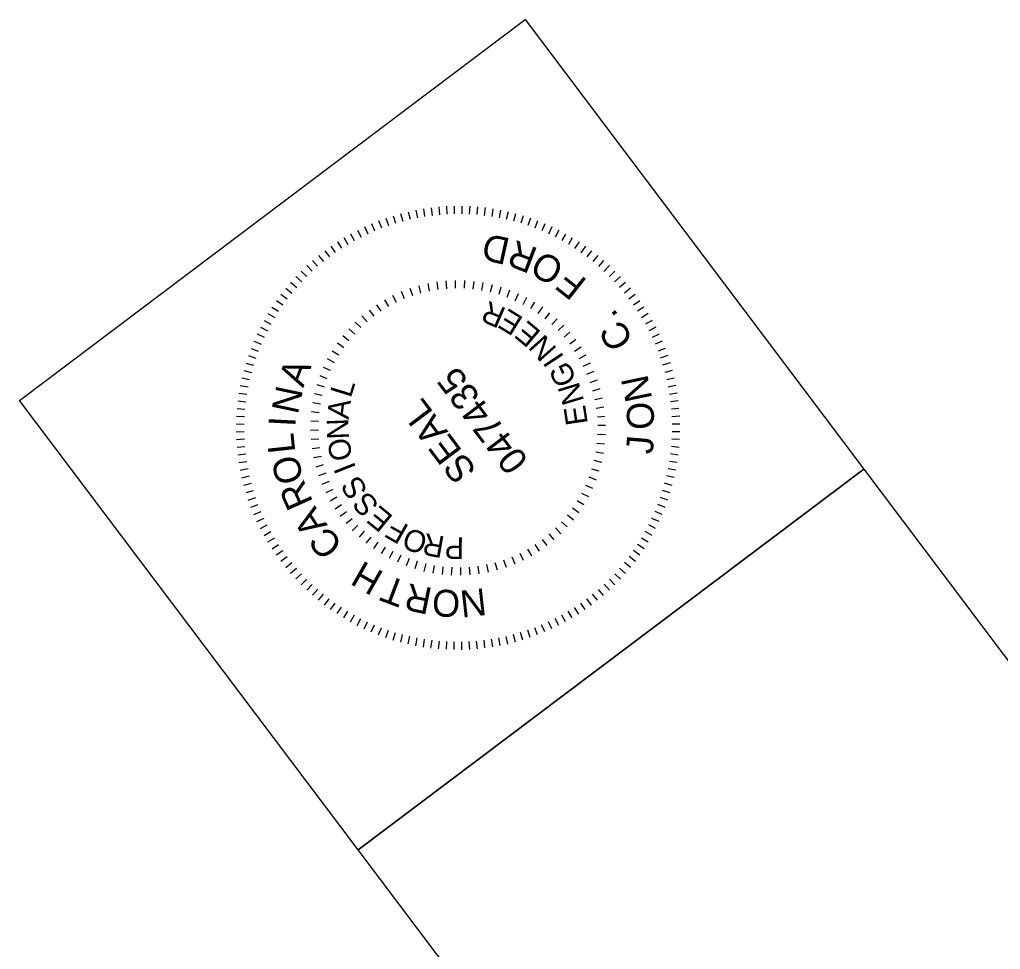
# Model space of a CAD drawing. Extents: x 1261689 to 1263694, y 776294 to 778298.
# Drawn here: x 1261689.1 to 1261863.3, y 777796.6 to 777961.8 of the extents above; entities that cross this region are included whole.
import ezdxf

# ---------------------------------------------------------------- set-up
doc = ezdxf.new("R2010")
doc.units = 0
doc.layers.add('Sheet Border Standard 30in CELL', color=7, linetype='Continuous')
doc.layers.add('Sheet PE Seal Cell', color=7, linetype='Continuous')

msp = doc.modelspace()

# ---------------------------------------------------------------- linework, layer by layer
at = {"layer": 'Sheet Border Standard 30in CELL'}
for points in [[(1261749.21, 777814.3), (1261689.06, 777894.15), (1261778.9, 777961.82), (1261839.04, 777881.96)], [(1261809.38, 777734.41), (1261749.21, 777814.3), (1261839.04, 777881.96), (1261899.22, 777802.07)]]:
    msp.add_lwpolyline(points, close=True, dxfattribs=at)
at = {"layer": 'Sheet PE Seal Cell'}
for p, q in [((1261760.81, 777928.21), (1261761, 777926.85)), ((1261762.17, 777928.39), (1261762.36, 777927.04)), ((1261763.56, 777928.54), (1261763.65, 777927.16)), ((1261764.91, 777928.66), (1261764.99, 777927.27)), ((1261766.28, 777928.67), (1261766.29, 777927.3)), ((1261767.65, 777928.67), (1261767.62, 777927.28)), ((1261769.05, 777928.65), (1261768.96, 777927.26)), ((1261770.4, 777928.53), (1261770.28, 777927.18)), ((1261771.75, 777928.41), (1261771.59, 777927.03)), ((1261773.12, 777928.18), (1261772.93, 777926.84)), ((1261754.15, 777926.55), (1261754.58, 777925.25)), ((1261755.44, 777926.97), (1261755.83, 777925.66)), ((1261756.76, 777927.37), (1261757.12, 777926.02)), ((1261758.11, 777927.66), (1261758.42, 777926.35)), ((1261759.44, 777927.95), (1261759.73, 777926.61)), ((1261774.49, 777927.95), (1261774.24, 777926.62)), ((1261775.83, 777927.69), (1261775.53, 777926.33)), ((1261777.18, 777927.33), (1261776.82, 777925.99)), ((1261778.5, 777926.95), (1261778.11, 777925.63)), ((1261779.81, 777926.56), (1261779.35, 777925.25)), ((1261750.31, 777925.03), (1261750.91, 777923.75)), ((1261751.58, 777925.57), (1261752.12, 777924.3)), ((1261752.85, 777926.11), (1261753.35, 777924.81)), ((1261781.07, 777926.07), (1261780.61, 777924.77)), ((1261782.36, 777925.54), (1261781.82, 777924.3)), ((1261783.63, 777924.99), (1261783.03, 777923.71)), ((1261746.68, 777923.08), (1261747.4, 777921.89)), ((1261747.86, 777923.73), (1261748.52, 777922.55)), ((1261749.09, 777924.42), (1261749.73, 777923.16)), ((1261784.84, 777924.41), (1261784.22, 777923.16)), ((1261786.07, 777923.72), (1261785.41, 777922.55)), ((1261787.25, 777923.05), (1261786.57, 777921.88)), ((1261744.35, 777921.56), (1261745.15, 777920.42)), ((1261745.51, 777922.32), (1261746.24, 777921.18)), ((1261788.45, 777922.32), (1261787.67, 777921.14)), ((1261789.57, 777921.56), (1261788.76, 777920.4)), ((1261742.16, 777919.91), (1261743.04, 777918.83)), ((1261743.27, 777920.75), (1261744.11, 777919.64)), ((1261790.66, 777920.76), (1261789.86, 777919.67)), ((1261791.77, 777919.91), (1261790.9, 777918.84)), ((1261740.1, 777918.12), (1261741.04, 777917.1)), ((1261741.11, 777919), (1261742, 777917.99)), ((1261792.8, 777919.02), (1261791.9, 777917.98)), ((1261793.85, 777918.12), (1261792.88, 777917.09)), ((1261738.14, 777916.18), (1261739.18, 777915.21)), ((1261739.11, 777917.13), (1261740.06, 777916.17)), ((1261794.83, 777917.11), (1261793.87, 777916.17)), ((1261795.79, 777916.17), (1261794.77, 777915.22)), ((1261737.21, 777915.17), (1261738.29, 777914.23)), ((1261760.37, 777913.19), (1261760.02, 777914.53)), ((1261761.89, 777913.54), (1261761.62, 777914.96)), ((1261763.41, 777913.85), (1261763.22, 777915.21)), ((1261764.97, 777914.01), (1261764.86, 777915.43)), ((1261766.52, 777914.1), (1261766.51, 777915.46)), ((1261768.09, 777914.08), (1261768.14, 777915.44)), ((1261769.65, 777913.93), (1261769.81, 777915.31)), ((1261771.19, 777913.71), (1261771.42, 777915.08)), ((1261772.73, 777913.43), (1261773.05, 777914.75)), ((1261774.24, 777913.01), (1261774.64, 777914.32)), ((1261796.7, 777915.11), (1261795.66, 777914.2)), ((1261735.48, 777913.03), (1261736.59, 777912.19)), ((1261736.35, 777914.1), (1261737.42, 777913.23)), ((1261756.03, 777911.53), (1261755.39, 777912.79)), ((1261757.46, 777912.19), (1261756.89, 777913.49)), ((1261758.91, 777912.73), (1261758.44, 777914.07)), ((1261775.7, 777912.5), (1261776.17, 777913.8)), ((1261777.12, 777911.88), (1261777.72, 777913.17)), ((1261778.53, 777911.2), (1261779.19, 777912.48)), ((1261797.58, 777914.1), (1261796.5, 777913.23)), ((1261798.42, 777912.99), (1261797.31, 777912.15)), ((1261733.9, 777910.75), (1261735.05, 777910.01)), ((1261734.7, 777911.9), (1261735.83, 777911.12)), ((1261753.28, 777910), (1261752.53, 777911.16)), ((1261754.64, 777910.84), (1261753.95, 777912)), ((1261779.87, 777910.48), (1261780.61, 777911.63)), ((1261781.18, 777909.6), (1261782, 777910.76)), ((1261799.26, 777911.88), (1261798.12, 777911.08)), ((1261799.99, 777910.75), (1261798.82, 777910)), ((1261733.19, 777909.62), (1261734.38, 777908.9)), ((1261750.8, 777908.13), (1261749.89, 777909.18)), ((1261752.03, 777909.12), (1261751.2, 777910.22)), ((1261782.42, 777908.68), (1261783.29, 777909.74)), ((1261800.75, 777909.58), (1261799.56, 777908.86)), ((1261732.5, 777908.37), (1261733.71, 777907.73)), ((1261749.66, 777907.09), (1261748.7, 777908.05)), ((1261783.61, 777907.65), (1261784.58, 777908.68)), ((1261784.72, 777906.57), (1261785.75, 777907.53)), ((1261801.43, 777908.36), (1261800.25, 777907.7)), ((1261731.27, 777905.96), (1261732.48, 777905.37)), ((1261731.85, 777907.17), (1261733.1, 777906.55)), ((1261747.58, 777904.75), (1261746.49, 777905.66)), ((1261748.62, 777905.94), (1261747.54, 777906.88)), ((1261785.79, 777905.39), (1261786.84, 777906.3)), ((1261802.09, 777907.17), (1261800.83, 777906.53)), ((1261802.67, 777905.92), (1261801.42, 777905.35)), ((1261730.68, 777904.66), (1261731.96, 777904.14)), ((1261746.66, 777903.51), (1261745.51, 777904.33)), ((1261786.79, 777904.23), (1261787.9, 777905.06)), ((1261803.24, 777904.68), (1261801.97, 777904.14)), ((1261729.7, 777902.13), (1261731.01, 777901.68)), ((1261730.19, 777903.4), (1261731.45, 777902.91)), ((1261745.79, 777902.2), (1261744.6, 777902.91)), ((1261787.66, 777902.91), (1261788.8, 777903.7)), ((1261788.47, 777901.59), (1261789.7, 777902.28)), ((1261803.75, 777903.38), (1261802.48, 777902.91)), ((1261804.22, 777902.11), (1261802.88, 777901.65)), ((1261729.28, 777900.8), (1261730.59, 777900.41)), ((1261745.02, 777900.83), (1261743.78, 777901.52)), ((1261789.2, 777900.23), (1261790.49, 777900.83)), ((1261804.64, 777900.82), (1261803.29, 777900.4)), ((1261728.89, 777899.48), (1261730.24, 777899.12)), ((1261743.73, 777898.01), (1261742.43, 777898.53)), ((1261744.31, 777899.46), (1261743.06, 777900.02)), ((1261789.86, 777898.8), (1261791.13, 777899.34)), ((1261805.01, 777899.47), (1261803.69, 777899.14)), ((1261728.27, 777896.79), (1261729.64, 777896.57)), ((1261728.57, 777898.16), (1261729.93, 777897.86)), ((1261743.22, 777896.54), (1261741.91, 777896.93)), ((1261790.4, 777897.36), (1261791.74, 777897.82)), ((1261805.36, 777898.12), (1261804.02, 777897.84)), ((1261805.65, 777896.79), (1261804.28, 777896.53)), ((1261728.02, 777895.46), (1261729.42, 777895.26)), ((1261742.83, 777895.06), (1261741.47, 777895.35)), ((1261790.89, 777895.85), (1261792.2, 777896.25)), ((1261805.88, 777895.45), (1261804.51, 777895.2)), ((1261727.86, 777894.08), (1261729.24, 777893.92)), ((1261742.51, 777893.49), (1261741.14, 777893.72)), ((1261791.24, 777894.33), (1261792.63, 777894.64)), ((1261806.06, 777894.09), (1261804.71, 777893.91)), ((1261727.7, 777892.7), (1261729.09, 777892.61)), ((1261742.29, 777891.95), (1261740.91, 777892.11)), ((1261791.51, 777892.78), (1261792.88, 777893.04)), ((1261806.21, 777892.7), (1261804.86, 777892.58)), ((1261727.59, 777889.98), (1261728.94, 777889.92)), ((1261727.61, 777891.38), (1261729, 777891.29)), ((1261742.18, 777890.42), (1261740.79, 777890.45)), ((1261791.71, 777891.25), (1261793.06, 777891.37)), ((1261806.33, 777891.35), (1261804.94, 777891.27)), ((1261806.37, 777889.95), (1261805, 777889.93)), ((1261727.56, 777888.57), (1261728.97, 777888.62)), ((1261742.17, 777888.85), (1261740.77, 777888.81)), ((1261791.75, 777888.17), (1261793.14, 777888.08)), ((1261791.77, 777889.74), (1261793.14, 777889.76)), ((1261806.37, 777888.57), (1261804.98, 777888.6)), ((1261727.6, 777887.24), (1261728.99, 777887.32)), ((1261742.25, 777887.3), (1261740.83, 777887.19)), ((1261791.63, 777886.58), (1261792.98, 777886.46)), ((1261806.32, 777887.21), (1261804.93, 777887.3)), ((1261727.69, 777885.86), (1261729.1, 777885.98)), ((1261727.84, 777884.47), (1261729.23, 777884.69)), ((1261742.41, 777885.74), (1261741.05, 777885.55)), ((1261791.41, 777885.03), (1261792.78, 777884.8)), ((1261806.07, 777884.44), (1261804.7, 777884.67)), ((1261806.23, 777885.82), (1261804.85, 777885.98)), ((1261728.02, 777883.11), (1261729.42, 777883.33)), ((1261742.68, 777884.19), (1261741.3, 777883.95)), ((1261791.1, 777883.53), (1261792.42, 777883.21)), ((1261805.88, 777883.1), (1261804.51, 777883.33)), ((1261728.24, 777881.78), (1261729.65, 777882.06)), ((1261743.01, 777882.71), (1261741.7, 777882.32)), ((1261743.49, 777881.21), (1261742.19, 777880.77)), ((1261790.68, 777882.02), (1261791.99, 777881.63)), ((1261805.62, 777881.77), (1261804.29, 777882.02)), ((1261728.56, 777880.41), (1261729.91, 777880.75)), ((1261728.89, 777879.09), (1261730.24, 777879.45)), ((1261744.03, 777879.76), (1261742.77, 777879.22)), ((1261790.17, 777880.56), (1261791.5, 777880.06)), ((1261805.01, 777879.07), (1261803.66, 777879.44)), ((1261805.37, 777880.44), (1261804, 777880.73)), ((1261729.29, 777877.77), (1261730.6, 777878.16)), ((1261744.7, 777878.33), (1261743.47, 777877.72)), ((1261788.9, 777877.69), (1261790.16, 777877.07)), ((1261789.58, 777879.1), (1261790.84, 777878.54)), ((1261804.66, 777877.73), (1261803.3, 777878.15)), ((1261729.68, 777876.45), (1261731.01, 777876.91)), ((1261745.42, 777876.97), (1261744.22, 777876.25)), ((1261788.11, 777876.36), (1261789.3, 777875.65)), ((1261804.23, 777876.46), (1261802.92, 777876.91)), ((1261730.15, 777875.18), (1261731.46, 777875.68)), ((1261730.7, 777873.91), (1261731.96, 777874.45)), ((1261746.26, 777875.61), (1261745.1, 777874.86)), ((1261747.14, 777874.36), (1261746.04, 777873.53)), ((1261787.27, 777875.08), (1261788.43, 777874.27)), ((1261803.22, 777873.9), (1261801.97, 777874.45)), ((1261803.77, 777875.15), (1261802.44, 777875.65)), ((1261731.23, 777872.64), (1261732.52, 777873.24)), ((1261748.13, 777873.13), (1261747.05, 777872.26)), ((1261785.35, 777872.61), (1261786.35, 777871.68)), ((1261786.38, 777873.8), (1261787.44, 777872.93)), ((1261802.67, 777872.63), (1261801.41, 777873.19)), ((1261731.84, 777871.42), (1261733.06, 777872.03)), ((1261732.5, 777870.16), (1261733.71, 777870.85)), ((1261749.17, 777871.99), (1261748.17, 777871)), ((1261750.28, 777870.92), (1261749.38, 777869.87)), ((1261784.27, 777871.5), (1261785.23, 777870.47)), ((1261801.42, 777870.15), (1261800.22, 777870.86)), ((1261802.04, 777871.39), (1261800.83, 777872.04)), ((1261733.18, 777869.01), (1261734.38, 777869.73)), ((1261751.47, 777869.88), (1261750.6, 777868.82)), ((1261752.71, 777868.96), (1261751.94, 777867.83)), ((1261781.9, 777869.47), (1261782.73, 777868.37)), ((1261783.09, 777870.43), (1261784, 777869.38)), ((1261800.75, 777868.97), (1261799.55, 777869.7)), ((1261733.91, 777867.81), (1261735.08, 777868.57)), ((1261734.67, 777866.72), (1261735.81, 777867.52)), ((1261754.02, 777868.09), (1261753.28, 777866.94)), ((1261755.39, 777867.32), (1261754.74, 777866.11)), ((1261779.29, 777867.75), (1261779.98, 777866.52)), ((1261780.61, 777868.56), (1261781.36, 777867.4)), ((1261799.23, 777866.69), (1261798.1, 777867.47)), ((1261800, 777867.81), (1261798.84, 777868.56)), ((1261735.47, 777865.57), (1261736.58, 777866.41)), ((1261756.8, 777866.64), (1261756.21, 777865.42)), ((1261758.26, 777866.05), (1261757.73, 777864.76)), ((1261759.69, 777865.58), (1261759.27, 777864.25)), ((1261775.03, 777865.86), (1261775.49, 777864.52)), ((1261776.5, 777866.36), (1261777.04, 777865.1)), ((1261777.93, 777867.02), (1261778.5, 777865.77)), ((1261798.46, 777865.56), (1261797.34, 777866.41)), ((1261736.35, 777864.49), (1261737.43, 777865.37)), ((1261737.19, 777863.45), (1261738.24, 777864.37)), ((1261761.21, 777865.16), (1261760.88, 777863.78)), ((1261762.73, 777864.81), (1261762.47, 777863.48)), ((1261764.28, 777864.59), (1261764.12, 777863.21)), ((1261765.84, 777864.51), (1261765.75, 777863.12)), ((1261767.38, 777864.47), (1261767.39, 777863.1)), ((1261768.93, 777864.56), (1261769.07, 777863.16)), ((1261770.48, 777864.71), (1261770.67, 777863.35)), ((1261772.03, 777864.98), (1261772.32, 777863.63)), ((1261773.52, 777865.38), (1261773.88, 777864.04)), ((1261796.72, 777863.42), (1261795.65, 777864.36)), ((1261797.58, 777864.49), (1261796.52, 777865.36)), ((1261738.14, 777862.43), (1261739.16, 777863.37)), ((1261739.09, 777861.41), (1261740.09, 777862.39)), ((1261794.81, 777861.39), (1261793.84, 777862.39)), ((1261795.79, 777862.42), (1261794.79, 777863.34)), ((1261740.09, 777860.47), (1261741.02, 777861.48)), ((1261741.09, 777859.54), (1261742.03, 777860.61)), ((1261792.81, 777859.52), (1261791.9, 777860.56)), ((1261793.84, 777860.47), (1261792.89, 777861.49)), ((1261742.16, 777858.68), (1261743.03, 777859.75)), ((1261743.23, 777857.8), (1261744.08, 777858.92)), ((1261790.69, 777857.8), (1261789.85, 777858.91)), ((1261791.74, 777858.65), (1261790.86, 777859.73)), ((1261744.32, 777857), (1261745.14, 777858.16)), ((1261745.49, 777856.27), (1261746.23, 777857.42)), ((1261746.64, 777855.51), (1261747.37, 777856.71)), ((1261787.25, 777855.51), (1261786.54, 777856.7)), ((1261788.41, 777856.21), (1261787.66, 777857.37)), ((1261789.55, 777857), (1261788.75, 777858.14)), ((1261747.85, 777854.8), (1261748.53, 777856.04)), ((1261749.05, 777854.15), (1261749.71, 777855.43)), ((1261784.85, 777854.17), (1261784.23, 777855.39)), ((1261786.06, 777854.8), (1261785.37, 777856.01)), ((1261750.27, 777853.57), (1261750.89, 777854.81)), ((1261751.53, 777853.02), (1261752.12, 777854.29)), ((1261752.82, 777852.49), (1261753.35, 777853.78)), ((1261754.13, 777852.03), (1261754.58, 777853.34)), ((1261779.78, 777852.04), (1261779.35, 777853.34)), ((1261781.08, 777852.48), (1261780.58, 777853.78)), ((1261782.35, 777853.02), (1261781.81, 777854.29)), ((1261783.62, 777853.56), (1261783.02, 777854.84)), ((1261755.42, 777851.58), (1261755.85, 777852.92)), ((1261756.78, 777851.22), (1261757.1, 777852.54)), ((1261758.11, 777850.9), (1261758.4, 777852.26)), ((1261759.43, 777850.57), (1261759.7, 777851.97)), ((1261760.8, 777850.34), (1261761, 777851.75)), ((1261762.14, 777850.16), (1261762.34, 777851.57)), ((1261771.72, 777850.18), (1261771.58, 777851.55)), ((1261773.13, 777850.38), (1261772.9, 777851.72)), ((1261774.46, 777850.61), (1261774.2, 777851.98)), ((1261775.82, 777850.86), (1261775.51, 777852.24)), ((1261777.17, 777851.22), (1261776.81, 777852.57)), ((1261778.46, 777851.59), (1261778.06, 777852.9)), ((1261763.49, 777850.03), (1261763.65, 777851.41)), ((1261764.88, 777849.94), (1261764.97, 777851.33)), ((1261766.25, 777849.88), (1261766.27, 777851.28)), ((1261767.65, 777849.86), (1261767.6, 777851.27)), ((1261769.02, 777849.93), (1261768.95, 777851.32)), ((1261770.4, 777850.01), (1261770.25, 777851.4))]:
    msp.add_line(p, q, dxfattribs=at)

# ---------------------------------------------------------------- texts
for s, height, rotation, p in [('D', 4.79, 167.4842, (1261776.43, 777922.88)), ('R', 4.79, 158.8526, (1261781.37, 777921.08)), ('O', 4.79, 149.9332, (1261786.12, 777918.47)), ('F', 4.79, 141.7332, (1261790.08, 777915.44)), ('R', 3.88, 156.6864, (1261775.69, 777910.44)), ('E', 3.88, 148.3844, (1261778.75, 777908.78)), ('.', 4.79, 128.1383, (1261795.58, 777909.27)), ('E', 3.88, 140.0823, (1261781.89, 777906.29)), ('C', 4.79, 119.5067, (1261798.25, 777904.75)), ('N', 3.88, 131.7803, (1261784.65, 777903.33)), ('I', 3.88, 123.4782, (1261785.91, 777901.82)), ('A', 4.79, 68.9785, (1261739.43, 777896.32)), ('G', 3.88, 115.1762, (1261788.14, 777897.74)), ('047435', 4.791, 126.9874, (1261779.63, 777883.43)), ('L', 3.88, 72.7539, (1261747.89, 777894.47)), ('N', 3.88, 106.8742, (1261789.4, 777894.08)), ('N', 4.79, 101.7398, (1261801.48, 777894.46)), ('N', 4.79, 78.0086, (1261738.48, 777891.53)), ('A', 3.88, 82.4627, (1261747.49, 777890.7)), ('SEAL', 4.791, 126.9874, (1261770.41, 777881.74)), ('O', 4.79, 92.8205, (1261801.86, 777889.05)), ('E', 3.88, 98.5721, (1261790.03, 777890.05)), ('I', 4.79, 87.0386, (1261738.04, 777889.39)), ('N', 3.88, 92.1716, (1261747.59, 777887.3)), ('L', 4.79, 96.0686, (1261738.06, 777884.98)), ('O', 3.88, 101.8804, (1261748.27, 777883.85)), ('J', 4.79, 85.3397, (1261801.53, 777884.51)), ('O', 4.79, 105.0986, (1261739.59, 777880.01)), ('I', 3.88, 111.5892, (1261748.89, 777882.16)), ('R', 4.79, 114.1287, (1261741.27, 777876.12)), ('S', 3.88, 121.298, (1261751.03, 777878.13)), ('S', 3.88, 131.0069, (1261753.1, 777875.62)), ('A', 4.79, 123.1587, (1261743.83, 777871.99)), ('E', 3.88, 140.7157, (1261755.61, 777873.48)), ('C', 4.79, 132.1887, (1261746.72, 777868.64)), ('F', 3.88, 150.4245, (1261758.42, 777871.82)), ('O', 3.88, 160.1334, (1261761.84, 777870.31)), ('R', 3.88, 169.8422, (1261764.76, 777869.93)), ('P', 3.88, 179.551, (1261768.06, 777869.84)), ('H', 4.79, 150.2488, (1261753.99, 777863.51)), ('T', 4.79, 159.2788, (1261758.17, 777861.8)), ('R', 4.79, 168.3088, (1261762.61, 777860.76)), ('O', 4.79, 177.3388, (1261767.44, 777860.39)), ('N', 4.79, 186.3689, (1261771.69, 777860.82))]:
    msp.add_text(s, height=height, rotation=rotation, dxfattribs=at).set_placement(p)

doc.saveas('drawing.dxf')
